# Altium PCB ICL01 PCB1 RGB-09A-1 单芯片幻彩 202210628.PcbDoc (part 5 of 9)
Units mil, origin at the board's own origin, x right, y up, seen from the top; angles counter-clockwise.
Board outline 17436.43 x 6581.89 mil, 2 copper layers (Top Layer, Bottom Layer), stack 65.792 mil thick; 425 components, 516 nets, 1625 pads, 2772 vias.
Unrouted connection lines stored in the file: 1.
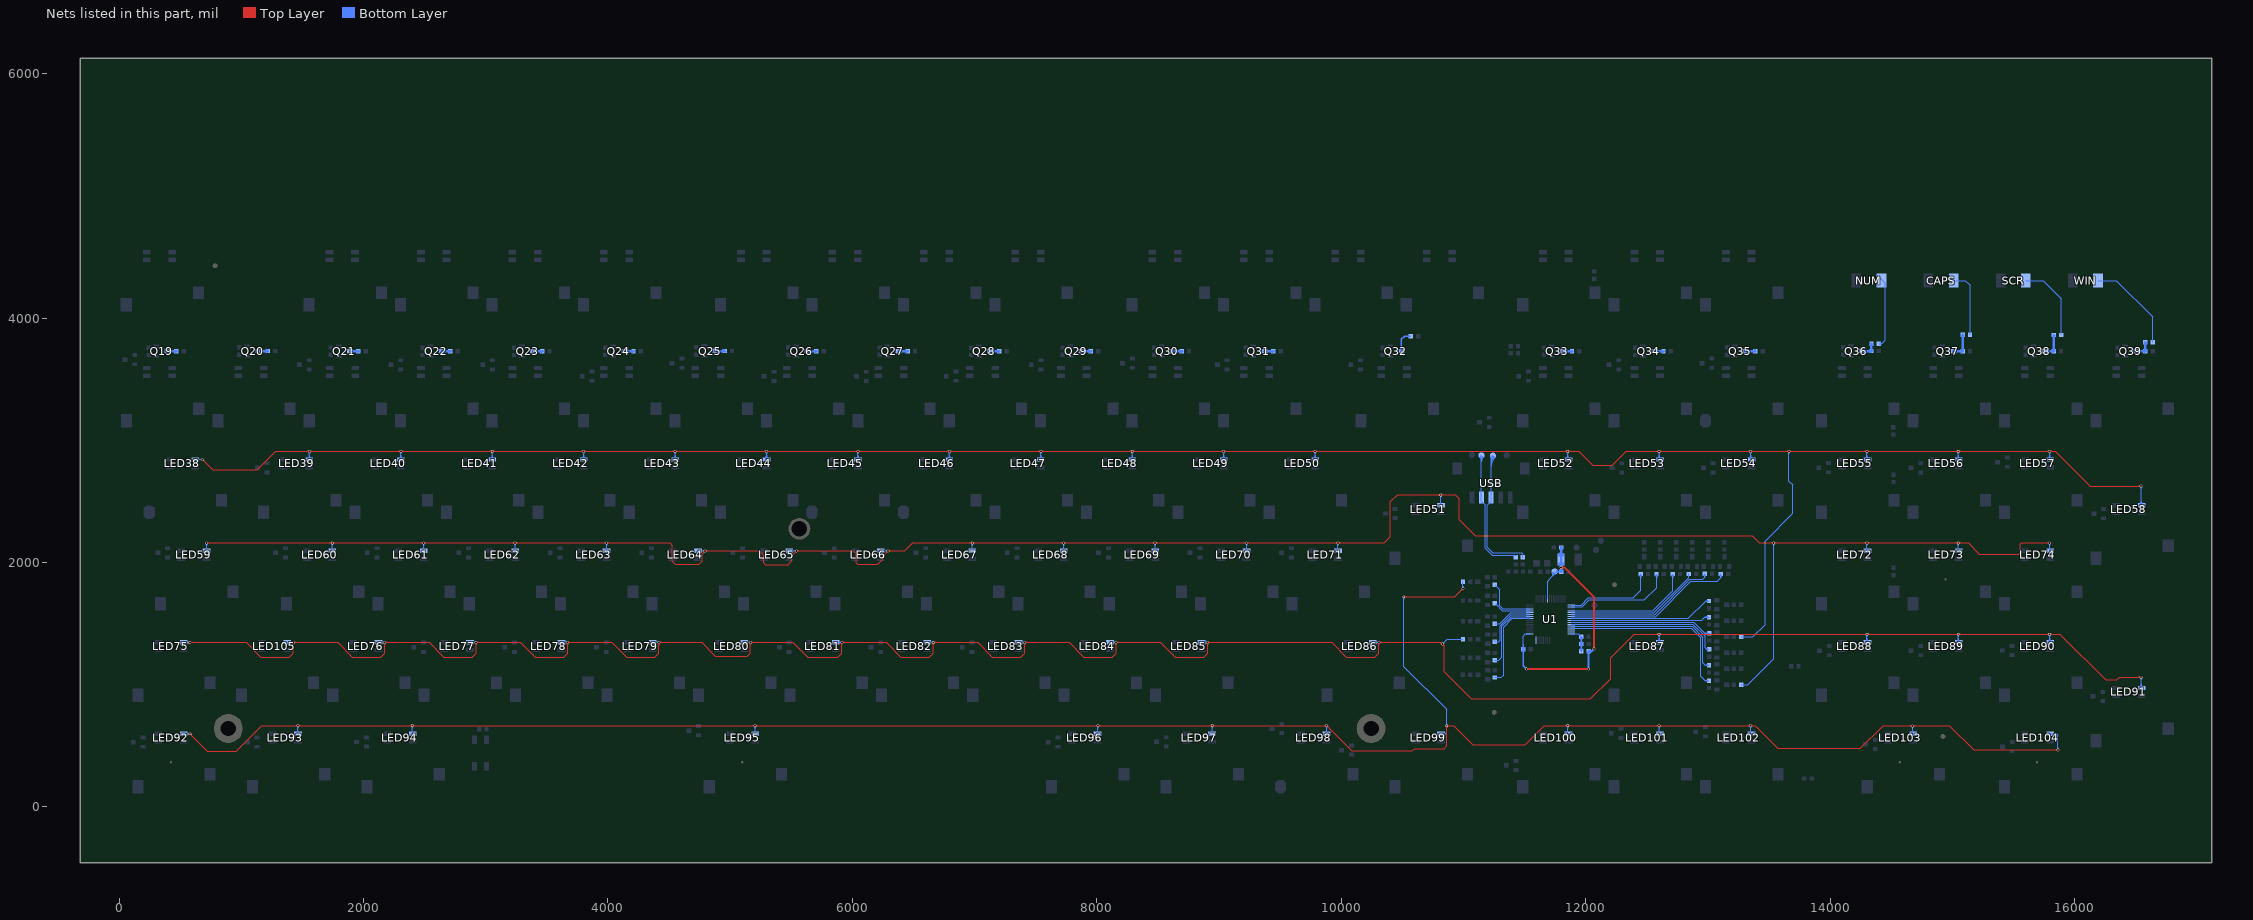
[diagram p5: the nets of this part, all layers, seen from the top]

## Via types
v1: diameter 23.62, hole 15.75, Top Layer to Bottom Layer, tented both sides, 2766 vias
v2: diameter 19.68, hole 11.81, Top Layer to Bottom Layer, tented both sides, 6 vias

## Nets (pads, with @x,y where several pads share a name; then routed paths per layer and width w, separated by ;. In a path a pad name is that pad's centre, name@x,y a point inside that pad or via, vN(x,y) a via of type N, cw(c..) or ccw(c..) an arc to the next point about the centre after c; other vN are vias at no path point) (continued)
GR2: LED38.G LED39.G LED40.G LED41.G LED42.G LED43.G LED44.G LED45.G LED46.G LED47.G LED48.G LED49.G LED50.G LED52.G LED53.G LED54.G LED55.G LED56.G LED57.G LED58.G RR9.2 | length 22150.5
  Top Layer w7.87: v1@682.41,2834.84 cw(c682.41,2815.83) 695.85,2829.28 cw(c709.3,2842.72) v1@690.29,2842.72 ; v1(682.41,2842.72) 768.34,2756.79 1132.05,2756.79 1284.13,2908.87 v1@11852.98,2908.87 ; 1538.45,2908.86 cw(c1538.45,2889.51) v1@1552.13,2903.19 ; 1538.93,2908.86 ccw(c1538.93,2927.53) v1@1552.13,2914.33 ; v1@1563.27,2903.19 cw(c1576.95,2889.51) 1576.95,2908.86 ; v1@1563.27,2914.33 ccw(c1576.47,2927.53) 1576.47,2908.86 ; 2286.48,2908.86 cw(c2286.48,2889.51) v1@2300.16,2903.19 ; 2286.96,2908.86 ccw(c2286.96,2927.53) v1@2300.16,2914.33 ; v1@2311.3,2903.19 cw(c2324.98,2889.51) 2324.98,2908.86 ; v1@2311.3,2914.33 ccw(c2324.5,2927.53) 2324.5,2908.86 ; 3034.51,2908.86 cw(c3034.51,2889.51) v1@3048.2,2903.19 ; 3035,2908.86 ccw(c3035,2927.53) v1@3048.2,2914.33 ; v1@3059.33,2903.19 cw(c3073.01,2889.51) 3073.01,2908.86 ; v1@3059.33,2914.33 ccw(c3072.53,2927.53) 3072.53,2908.86 ; 3782.54,2908.86 cw(c3782.54,2889.51) v1@3796.23,2903.19 ; 3783.03,2908.86 ccw(c3783.03,2927.53) v1@3796.23,2914.33 ; v1@3807.36,2903.19 cw(c3821.05,2889.51) 3821.05,2908.86 ; v1@3807.36,2914.33 ccw(c3820.56,2927.53) 3820.56,2908.86 ; 4530.58,2908.86 cw(c4530.58,2889.51) v1@4544.26,2903.19 ; 4531.06,2908.86 ccw(c4531.06,2927.53) v1@4544.26,2914.33 ; v1@4555.39,2903.19 cw(c4569.08,2889.51) 4569.08,2908.86 ; v1@4555.39,2914.33 ccw(c4568.59,2927.53) 4568.59,2908.86 ; 5278.61,2908.86 cw(c5278.61,2889.51) v1@5292.29,2903.19 ; 5279.09,2908.86 ccw(c5279.09,2927.53) v1@5292.29,2914.33 ; v1@5303.43,2903.19 cw(c5317.11,2889.51) 5317.11,2908.86 ; v1@5303.43,2914.33 ccw(c5316.63,2927.53) 5316.63,2908.86 ; 6026.64,2908.86 cw(c6026.64,2889.51) v1@6040.32,2903.19 ; 6027.12,2908.86 ccw(c6027.12,2927.53) v1@6040.32,2914.33 ; v1@6051.46,2903.19 cw(c6065.14,2889.51) 6065.14,2908.86 ; v1@6051.46,2914.33 ccw(c6064.66,2927.53) 6064.66,2908.86 ; 6774.67,2908.86 cw(c6774.67,2889.51) v1@6788.35,2903.19 ; 6775.15,2908.86 ccw(c6775.15,2927.53) v1@6788.35,2914.33 ; v1@6799.49,2903.19 cw(c6813.17,2889.51) 6813.17,2908.86 ; v1@6799.49,2914.33 ccw(c6812.69,2927.53) 6812.69,2908.86 ; 7522.7,2908.86 cw(c7522.7,2889.51) v1@7536.38,2903.19 ; 7523.18,2908.86 ccw(c7523.18,2927.53) v1@7536.38,2914.33 ; v1@7547.52,2903.19 cw(c7561.2,2889.51) 7561.2,2908.86 ; v1@7547.52,2914.33 ccw(c7560.72,2927.53) 7560.72,2908.86 ; 8270.73,2908.86 cw(c8270.73,2889.51) v1@8284.42,2903.19 ; 8271.22,2908.86 ccw(c8271.22,2927.53) v1@8284.42,2914.33 ; v1@8295.55,2903.19 cw(c8309.24,2889.51) 8309.24,2908.86 ; v1@8295.55,2914.33 ccw(c8308.75,2927.53) 8308.75,2908.86 ; 9018.76,2908.86 cw(c9018.76,2889.51) v1@9032.45,2903.19 ; 9019.25,2908.86 ccw(c9019.25,2927.53) v1@9032.45,2914.33 ; v1@9043.58,2903.19 cw(c9057.27,2889.51) 9057.27,2908.86 ; v1@9043.58,2914.33 ccw(c9056.78,2927.53) 9056.78,2908.86 ; 9766.8,2908.86 cw(c9766.8,2889.51) v1@9780.48,2903.19 ; 9767.28,2908.86 ccw(c9767.28,2927.53) v1@9780.48,2914.33 ; v1@9791.62,2903.19 cw(c9805.3,2889.51) 9805.3,2908.86 ; v1@9791.62,2914.33 ccw(c9804.82,2927.53) 9804.82,2908.86 ; 11833.71,2908.87 cw(c11833.71,2889.5) v1@11847.41,2903.19 ; 11834.22,2908.87 ccw(c11834.22,2927.52) v1@11847.41,2914.33 ; v1(11852.98,2908.76) 11941.7,2908.76 12055.64,2794.82 12217.49,2794.82 12331.53,2908.87 v1(13663.07,2908.87) 15842.45,2908.87 16126.95,2624.37 v1(16543.92,2624.37) ; v1@11858.54,2903.19 cw(c11871.99,2889.75) 11871.99,2908.76 cw(c11871.99,2927.77) v1@11858.54,2914.33 ; 12581.76,2908.86 cw(c12581.76,2889.51) v1@12595.44,2903.19 ; 12582.24,2908.86 ccw(c12582.24,2927.53) v1@12595.44,2914.33 ; v1@12606.58,2903.19 cw(c12620.26,2889.51) 12620.26,2908.86 ; v1@12606.58,2914.33 ccw(c12619.78,2927.53) 12619.78,2908.86 ; 13329.79,2908.86 cw(c13329.79,2889.51) v1@13343.47,2903.19 ; 13330.27,2908.86 ccw(c13330.27,2927.53) v1@13343.47,2914.33 ; v1@13354.61,2903.19 cw(c13368.29,2889.51) 13368.29,2908.86 ; v1@13354.61,2914.33 ccw(c13367.81,2927.53) 13367.81,2908.86 ; v1@13657.5,2903.3 ccw(c13644.06,2889.86) 13644.06,2908.87 ccw(c13644.06,2927.88) v1@13657.5,2914.43 ; v1@13668.64,2903.3 cw(c13682.08,2889.86) 13682.08,2908.87 cw(c13682.08,2927.88) v1@13668.64,2914.43 ; 14280.58,2908.86 cw(c14280.58,2889.51) v1@14294.26,2903.19 ; 14281.06,2908.86 ccw(c14281.06,2927.53) v1@14294.26,2914.33 ; v1@14305.39,2903.19 cw(c14319.08,2889.51) 14319.08,2908.86 ; v1@14305.39,2914.33 ccw(c14318.59,2927.53) 14318.59,2908.86 ; 15028.61,2908.86 cw(c15028.61,2889.51) v1@15042.29,2903.19 ; 15029.09,2908.86 ccw(c15029.09,2927.53) v1@15042.29,2914.33 ; v1@15053.43,2903.19 cw(c15067.11,2889.51) 15067.11,2908.86 ; v1@15053.43,2914.33 ccw(c15066.63,2927.53) 15066.63,2908.86 ; v1@15790.32,2903.29 ccw(c15776.88,2889.85) 15776.88,2908.86 ccw(c15776.88,2927.87) v1@15790.32,2914.43 ; v1@15801.46,2903.29 cw(c15814.9,2889.85) 15814.9,2908.86 cw(c15814.9,2927.87) v1@15801.46,2914.43 ; v1@16538.36,2618.8 ccw(c16524.91,2605.36) 16524.91,2624.37 ccw(c16524.91,2643.38) v1@16538.36,2629.94
  Bottom Layer w7.87: LED38.G@622.66,2842.72 v1(682.41,2842.72) ; v1@676.84,2837.15 ccw(c663.4,2823.71) 663.4,2842.72 ccw(c663.4,2861.73) v1@676.84,2848.29 ; LED39.G@1547.96,2852.46 ccw(c1524.43,2875.98) 1557.7,2875.98 ccw(c1590.97,2875.98) LED39.G@1567.44,2852.46 ; v1@1552.13,2903.19 cw(c1538.69,2889.75) 1557.7,2889.75 cw(c1576.71,2889.75) v1@1563.27,2903.19 ; LED39.G@1557.7,2842.72 v1(1557.7,2908.76) ; LED40.G@2295.99,2852.46 ccw(c2272.47,2875.98) 2305.73,2875.98 ccw(c2339,2875.98) LED40.G@2315.48,2852.46 ; v1@2300.16,2903.19 cw(c2286.72,2889.75) 2305.73,2889.75 cw(c2324.74,2889.75) v1@2311.3,2903.19 ; LED40.G@2305.73,2842.72 v1(2305.73,2908.76) ; LED41.G@3044.02,2852.46 ccw(c3020.5,2875.98) 3053.76,2875.98 ccw(c3087.03,2875.98) LED41.G@3063.51,2852.46 ; v1@3048.2,2903.19 cw(c3034.75,2889.75) 3053.76,2889.75 cw(c3072.77,2889.75) v1@3059.33,2903.19 ; LED41.G@3053.76,2842.72 v1(3053.76,2908.76) ; LED42.G@3792.05,2852.46 ccw(c3768.53,2875.98) 3801.8,2875.98 ccw(c3835.06,2875.98) LED42.G@3811.54,2852.46 ; v1@3796.23,2903.19 cw(c3782.79,2889.75) 3801.8,2889.75 cw(c3820.81,2889.75) v1@3807.36,2903.19 ; LED42.G@3801.8,2842.72 v1(3801.8,2908.76) ; LED43.G@4540.08,2852.46 ccw(c4516.56,2875.98) 4549.83,2875.98 ccw(c4583.09,2875.98) LED43.G@4559.57,2852.46 ; v1@4544.26,2903.19 cw(c4530.82,2889.75) 4549.83,2889.75 cw(c4568.84,2889.75) v1@4555.39,2903.19 ; LED43.G@4549.83,2842.72 v1(4549.83,2908.76) ; LED44.G@5288.12,2852.46 ccw(c5264.59,2875.98) 5297.86,2875.98 ccw(c5331.13,2875.98) LED44.G@5307.6,2852.46 ; v1@5292.29,2903.19 cw(c5278.85,2889.75) 5297.86,2889.75 cw(c5316.87,2889.75) v1@5303.43,2903.19 ; LED44.G@5297.86,2842.72 v1(5297.86,2908.76) ; LED45.G@6036.15,2852.46 ccw(c6012.62,2875.98) 6045.89,2875.98 ccw(c6079.16,2875.98) LED45.G@6055.63,2852.46 ; v1@6040.32,2903.19 cw(c6026.88,2889.75) 6045.89,2889.75 cw(c6064.9,2889.75) v1@6051.46,2903.19 ; LED45.G@6045.89,2842.72 v1(6045.89,2908.76) ; LED46.G@6784.18,2852.46 ccw(c6760.66,2875.98) 6793.92,2875.98 ccw(c6827.19,2875.98) LED46.G@6803.67,2852.46 ; v1@6788.35,2903.19 cw(c6774.91,2889.75) 6793.92,2889.75 cw(c6812.93,2889.75) v1@6799.49,2903.19 ; LED46.G@6793.92,2842.72 v1(6793.92,2908.76) ; LED47.G@7532.21,2852.46 ccw(c7508.69,2875.98) 7541.95,2875.98 ccw(c7575.22,2875.98) LED47.G@7551.7,2852.46 ; v1@7536.38,2903.19 cw(c7522.94,2889.75) 7541.95,2889.75 cw(c7560.96,2889.75) v1@7547.52,2903.19 ; LED47.G@7541.95,2842.72 v1(7541.95,2908.76) ; LED48.G@8280.24,2852.46 ccw(c8256.72,2875.98) 8289.98,2875.98 ccw(c8323.25,2875.98) LED48.G@8299.73,2852.46 ; v1@8284.42,2903.19 cw(c8270.98,2889.75) 8289.98,2889.75 cw(c8308.99,2889.75) v1@8295.55,2903.19 ; LED48.G@8289.98,2842.72 v1(8289.98,2908.76) ; LED49.G@9028.27,2852.46 ccw(c9004.75,2875.98) 9038.02,2875.98 ccw(c9071.28,2875.98) LED49.G@9047.76,2852.46 ; v1@9032.45,2903.19 cw(c9019.01,2889.75) 9038.02,2889.75 cw(c9057.03,2889.75) v1@9043.58,2903.19 ; LED49.G@9038.02,2842.72 v1(9038.02,2908.76) ; LED50.G@9776.3,2852.46 ccw(c9752.78,2875.98) 9786.05,2875.98 ccw(c9819.31,2875.98) LED50.G@9795.79,2852.46 ; v1@9780.48,2903.19 cw(c9767.04,2889.75) 9786.05,2889.75 cw(c9805.06,2889.75) v1@9791.62,2903.19 ; LED50.G@9786.05,2842.72 v1(9786.05,2908.76) ; LED52.G@11843.23,2852.46 ccw(c11819.71,2875.98) 11852.98,2875.98 ccw(c11886.24,2875.98) LED52.G@11862.72,2852.46 ; v1@11847.41,2903.19 cw(c11833.97,2889.75) 11852.98,2889.75 cw(c11871.99,2889.75) v1@11858.54,2903.19 ; LED52.G@11852.98,2842.72 v1(11852.98,2908.76) ; LED53.G@12591.26,2852.46 ccw(c12567.74,2875.98) 12601.01,2875.98 ccw(c12634.27,2875.98) LED53.G@12610.75,2852.46 ; v1@12595.44,2903.19 cw(c12582,2889.75) 12601.01,2889.75 cw(c12620.02,2889.75) v1@12606.58,2903.19 ; LED53.G@12601.01,2842.72 v1(12601.01,2908.76) ; RR9.2@13272.34,1391.22 13365.96,1391.22 13467.2,1492.46 13467.2,2175.6 13693.49,2401.88 13693.49,2634.35 13663.07,2664.77 v1(13663.07,2908.87) ; LED54.G@13339.3,2852.46 ccw(c13315.77,2875.98) 13349.04,2875.98 ccw(c13382.31,2875.98) LED54.G@13358.78,2852.46 ; v1@13343.47,2903.19 cw(c13330.03,2889.75) 13349.04,2889.75 cw(c13368.05,2889.75) v1@13354.61,2903.19 ; LED54.G@13349.04,2842.72 v1(13349.04,2908.76) ; v1@13657.5,2903.3 cw(c13644.06,2889.86) 13663.07,2889.86 cw(c13682.08,2889.86) v1@13668.64,2903.3 ; LED55.G@14290.08,2852.46 ccw(c14266.56,2875.98) 14299.83,2875.98 ccw(c14333.09,2875.98) LED55.G@14309.57,2852.46 ; v1@14294.26,2903.19 cw(c14280.82,2889.75) 14299.83,2889.75 cw(c14318.84,2889.75) v1@14305.39,2903.19 ; LED55.G@14299.83,2842.72 v1(14299.83,2908.76) ; LED56.G@15038.12,2852.46 ccw(c15014.59,2875.98) 15047.86,2875.98 ccw(c15081.13,2875.98) LED56.G@15057.6,2852.46 ; v1@15042.29,2903.19 cw(c15028.85,2889.75) 15047.86,2889.75 cw(c15066.87,2889.75) v1@15053.43,2903.19 ; LED56.G@15047.86,2842.72 v1(15047.86,2908.76) ; LED57.G@15786.15,2852.46 ccw(c15762.62,2875.98) 15795.89,2875.98 ccw(c15829.16,2875.98) LED57.G@15805.63,2852.46 ; v1@15790.32,2903.29 cw(c15776.88,2889.85) 15795.89,2889.85 cw(c15814.9,2889.85) v1@15801.46,2903.29 ; LED57.G@15795.89,2842.72 v1(15795.89,2908.86) ; LED58.G@16534.18,2478.45 ccw(c16510.66,2501.97) 16543.92,2501.97 ccw(c16577.19,2501.97) LED58.G@16553.67,2478.45 ; v1@16538.36,2618.8 cw(c16524.91,2605.36) 16543.92,2605.36 cw(c16562.93,2605.36) v1@16549.49,2618.8 ; LED58.G@16543.92,2468.7 v1(16543.92,2624.37)
GR3: LED51.G LED59.G LED60.G LED61.G LED62.G LED63.G LED64.G LED65.G LED66.G LED67.G LED68.G LED69.G LED70.G LED71.G LED72.G LED73.G LED74.G RR12.2 | length 20324.4
  Top Layer w7.87: v1@716.47,2160.83 4505.83,2160.83 4528.17,2138.49 4528.17,2009.39 4552.4,1985.16 4745.09,1985.16 4770.1,2010.17 4770.1,2069.15 v1(4795.64,2094.69) 5238.05,2094.69 5273.75,2058.98 5273.75,1996.1 5286.6,1983.25 5475.55,1983.25 5504.8,2012.5 5504.8,2055.82 v1(5543.67,2094.69) 6007.74,2094.69 6030.85,2071.58 6030.85,1999.66 6045.64,1984.88 6208.27,1984.88 6250.16,2026.77 6250.16,2053.15 v1(6291.7,2094.69) 6429.35,2094.69 6495.49,2160.83 10352.84,2160.83 10402.69,2210.68 10402.69,2494.94 10461.3,2553.55 10933.17,2553.55 10964.7,2522.02 10964.7,2350.29 11094.3,2220.69 13360.89,2220.69 13420.71,2160.88 13538.03,2160.88 v1(13538.07,2160.83) 15128.19,2160.83 15220.92,2068.1 15542.48,2068.1 15554.24,2079.85 15554.24,2149.74 15564.77,2160.27 v1(15795.85,2160.27) ; v1@722.03,2153.3 cw(c740.22,2135.11) 740.22,2160.83 ; v1@722.03,2164.44 ccw(c730.73,2173.13) 730.73,2160.83 ; v1@1739.14,2155.27 ccw(c1725.7,2141.83) 1725.7,2160.84 ccw(c1725.7,2179.85) v1@1739.14,2166.41 ; v1@1750.28,2155.27 cw(c1763.72,2141.83) 1763.72,2160.84 cw(c1763.72,2179.85) v1@1750.28,2166.41 ; v1@2487.17,2155.27 ccw(c2473.73,2141.83) 2473.73,2160.84 ccw(c2473.73,2179.85) v1@2487.17,2166.41 ; v1@2498.31,2155.27 cw(c2511.75,2141.83) 2511.75,2160.84 cw(c2511.75,2179.85) v1@2498.31,2166.41 ; v1@3235.2,2155.27 ccw(c3221.76,2141.83) 3221.76,2160.84 ccw(c3221.76,2179.85) v1@3235.2,2166.41 ; v1@3246.34,2155.27 cw(c3259.78,2141.83) 3259.78,2160.84 cw(c3259.78,2179.85) v1@3246.34,2166.41 ; v1@3983.24,2155.27 ccw(c3969.79,2141.83) 3969.79,2160.84 ccw(c3969.79,2179.85) v1@3983.24,2166.41 ; v1@3994.37,2155.27 cw(c4007.81,2141.83) 4007.81,2160.84 cw(c4007.81,2179.85) v1@3994.37,2166.41 ; v1@4787.76,2094.69 cw(c4768.75,2094.69) 4782.19,2081.25 cw(c4795.64,2067.8) v1@4795.64,2086.81 ; v1@4801.2,2089.12 cw(c4814.65,2075.68) 4814.65,2094.69 cw(c4814.65,2113.7) v1@4801.2,2100.25 ; v1@5535.79,2094.69 cw(c5516.78,2094.69) 5530.23,2081.25 cw(c5543.67,2067.8) v1@5543.67,2086.81 ; v1@5549.24,2089.12 cw(c5562.68,2075.68) 5562.68,2094.69 cw(c5562.68,2113.7) v1@5549.24,2100.25 ; v1@6283.83,2094.69 cw(c6264.82,2094.69) 6278.26,2081.25 cw(c6291.7,2067.8) v1@6291.7,2086.81 ; v1@6297.27,2089.12 cw(c6310.71,2075.68) 6310.71,2094.69 cw(c6310.71,2113.7) v1@6297.27,2100.25 ; v1@6975.36,2155.27 ccw(c6961.92,2141.83) 6961.92,2160.84 ccw(c6961.92,2179.85) v1@6975.36,2166.41 ; v1@6986.5,2155.27 cw(c6999.94,2141.83) 6999.94,2160.84 cw(c6999.94,2179.85) v1@6986.5,2166.41 ; v1@7723.39,2155.27 ccw(c7709.95,2141.83) 7709.95,2160.84 ccw(c7709.95,2179.85) v1@7723.39,2166.41 ; v1@7734.53,2155.27 cw(c7747.97,2141.83) 7747.97,2160.84 cw(c7747.97,2179.85) v1@7734.53,2166.41 ; v1@8471.42,2155.27 ccw(c8457.98,2141.83) 8457.98,2160.84 ccw(c8457.98,2179.85) v1@8471.42,2166.41 ; v1@8482.56,2155.27 cw(c8496,2141.83) 8496,2160.84 cw(c8496,2179.85) v1@8482.56,2166.41 ; v1@9219.46,2155.27 ccw(c9206.01,2141.83) 9206.01,2160.84 ccw(c9206.01,2179.85) v1@9219.46,2166.41 ; v1@9230.59,2155.27 cw(c9244.03,2141.83) 9244.03,2160.84 cw(c9244.03,2179.85) v1@9230.59,2166.41 ; v1@9967.49,2155.27 ccw(c9954.05,2141.83) 9954.05,2160.84 ccw(c9954.05,2179.85) v1@9967.49,2166.41 ; v1@9978.62,2155.27 cw(c9992.07,2141.83) 9992.07,2160.84 cw(c9992.07,2179.85) v1@9978.62,2166.41 ; 10795.03,2553.55 ccw(c10795.03,2572.71) v1@10808.58,2559.16 ; 10795.25,2553.55 cw(c10795.25,2534.7) v1@10808.58,2548.03 ; v1@10819.72,2548.03 cw(c10833.05,2534.7) 10833.05,2553.55 ; v1@10819.72,2559.16 ccw(c10833.27,2572.71) 10833.27,2553.55 ; 13518.96,2160.88 cw(c13518.96,2141.73) v1@13532.5,2155.27 ; 13519.16,2160.88 ccw(c13519.16,2179.75) v1@13532.5,2166.4 ; v1@13543.64,2155.27 cw(c13557.08,2141.83) 13557.08,2160.83 cw(c13557.08,2179.84) v1@13543.64,2166.4 ; v1@14294.26,2155.27 ccw(c14280.82,2141.83) 14280.82,2160.84 ccw(c14280.82,2179.85) v1@14294.26,2166.41 ; v1@14305.39,2155.27 cw(c14318.84,2141.83) 14318.84,2160.84 cw(c14318.84,2179.85) v1@14305.39,2166.41 ; v1@15042.29,2155.27 ccw(c15028.85,2141.83) 15028.85,2160.84 ccw(c15028.85,2179.85) v1@15042.29,2166.41 ; v1@15053.43,2155.27 cw(c15066.87,2141.83) 15066.87,2160.84 cw(c15066.87,2179.85) v1@15053.43,2166.41 ; v1@15790.28,2154.71 ccw(c15776.84,2141.26) 15776.84,2160.27 ccw(c15776.84,2179.28) v1@15790.28,2165.84
  Bottom Layer w7.87: v1@710.9,2153.3 cw(c698.18,2140.58) 716.17,2140.58 ; LED59.G@716.17,2094.69 v1@716.17,2160.24 ; 716.17,2139.14 cw(c736.2,2139.14) v1@722.03,2153.3 ; v1@1739.14,2155.27 cw(c1725.7,2141.83) 1744.71,2141.83 cw(c1763.72,2141.83) v1@1750.28,2155.27 ; LED60.G@1744.71,2094.69 v1(1744.71,2160.84) ; v1@2487.17,2155.27 cw(c2473.73,2141.83) 2492.74,2141.83 cw(c2511.75,2141.83) v1@2498.31,2155.27 ; LED61.G@2492.74,2094.69 v1(2492.74,2160.84) ; v1@3235.2,2155.27 cw(c3221.76,2141.83) 3240.77,2141.83 cw(c3259.78,2141.83) v1@3246.34,2155.27 ; LED62.G@3240.77,2094.69 v1(3240.77,2160.84) ; v1@3983.24,2155.27 cw(c3969.79,2141.83) 3988.8,2141.83 cw(c4007.81,2141.83) v1@3994.37,2155.27 ; LED63.G@3988.8,2094.69 v1(3988.8,2160.84) ; LED64.G@4736.83,2094.69 v1(4795.64,2094.69) ; v1@4790.07,2089.12 ccw(c4776.63,2075.68) 4776.63,2094.69 ccw(c4776.63,2113.7) v1@4790.07,2100.25 ; LED65.G@5484.87,2094.69 v1(5543.67,2094.69) ; v1@5538.1,2089.12 ccw(c5524.66,2075.68) 5524.66,2094.69 ccw(c5524.66,2113.7) v1@5538.1,2100.25 ; LED66.G@6232.9,2094.69 v1(6291.7,2094.69) ; v1@6286.13,2089.12 ccw(c6272.69,2075.68) 6272.69,2094.69 ccw(c6272.69,2113.7) v1@6286.13,2100.25 ; v1@6975.36,2155.27 cw(c6961.92,2141.83) 6980.93,2141.83 cw(c6999.94,2141.83) v1@6986.5,2155.27 ; LED67.G@6980.93,2094.69 v1(6980.93,2160.84) ; v1@7723.39,2155.27 cw(c7709.95,2141.83) 7728.96,2141.83 cw(c7747.97,2141.83) v1@7734.53,2155.27 ; LED68.G@7728.96,2094.69 v1(7728.96,2160.84) ; v1@8471.42,2155.27 cw(c8457.98,2141.83) 8476.99,2141.83 cw(c8496,2141.83) v1@8482.56,2155.27 ; LED69.G@8476.99,2094.69 v1(8476.99,2160.84) ; v1@9219.46,2155.27 cw(c9206.01,2141.83) 9225.02,2141.83 cw(c9244.03,2141.83) v1@9230.59,2155.27 ; LED70.G@9225.02,2094.69 v1(9225.02,2160.84) ; v1@9967.49,2155.27 cw(c9954.05,2141.83) 9973.06,2141.83 cw(c9992.07,2141.83) v1@9978.62,2155.27 ; LED71.G@9973.06,2094.69 v1(9973.06,2160.84) ; v1@10808.58,2548.03 cw(c10795.14,2534.59) 10814.15,2534.59 cw(c10833.16,2534.59) v1@10819.72,2548.03 ; LED51.G@10814.15,2468.64 v1(10814.15,2553.6) ; RR12.2@13272.34,998.6 13325.16,998.6 13538.07,1211.51 v1(13538.07,2160.83) ; v1@13532.5,2155.27 cw(c13519.06,2141.83) 13538.07,2141.83 cw(c13557.08,2141.83) v1@13543.64,2155.27 ; v1@14294.26,2155.27 cw(c14280.82,2141.83) 14299.83,2141.83 cw(c14318.84,2141.83) v1@14305.39,2155.27 ; LED72.G@14299.83,2094.69 v1(14299.83,2160.84) ; v1@15042.29,2155.27 cw(c15028.85,2141.83) 15047.86,2141.83 cw(c15066.87,2141.83) v1@15053.43,2155.27 ; LED73.G@15047.86,2094.69 v1(15047.86,2160.84) ; v1@15790.28,2154.71 cw(c15776.75,2141.17) 15795.89,2141.17 ; LED74.G@15795.89,2094.69 v1@15795.89,2160.34 ; 15795.89,2141.36 cw(c15814.76,2141.36) v1@15801.42,2154.71
  other v1: 716.47,2158.87
GR4: LED75.G LED76.G LED77.G LED78.G LED79.G LED80.G LED81.G LED82.G LED83.G LED84.G LED85.G LED86.G LED87.G LED88.G LED89.G LED90.G LED91.G LED105.G RR15.2 | length 21513
  Top Layer w7.87: v1(579.16,1345.72) 1040.61,1345.72 1160.37,1225.97 1393.14,1225.97 1425.62,1258.44 v1(1425.62,1345.72) 1788.64,1345.72 1908.4,1225.97 2141.17,1225.97 2173.65,1258.44 v1(2173.65,1345.72) 2536.68,1345.72 2656.43,1225.97 2889.2,1225.97 2921.68,1258.44 v1(2921.68,1345.72) 3284.71,1345.72 3404.47,1225.97 3637.23,1225.97 3669.71,1258.44 v1(3669.71,1345.72) 4032.74,1345.72 4152.5,1225.97 4385.26,1225.97 4417.74,1258.44 v1(4417.74,1345.72) 4766.62,1345.72 4878.03,1234.31 5141.64,1234.31 5165.77,1258.44 v1(5165.77,1345.72) 5514.14,1345.72 5633.9,1225.97 5881.33,1225.97 5913.81,1258.44 v1(5913.81,1345.72) 6276.83,1345.72 6396.59,1225.97 6629.36,1225.97 6661.84,1258.44 v1(6661.84,1345.72) 7024.86,1345.72 7144.62,1225.97 7377.39,1225.97 7409.87,1258.44 v1(7409.87,1345.72) 7772.9,1345.72 7892.65,1225.97 8125.42,1225.97 8157.9,1258.44 v1(8157.9,1345.72) 8520.93,1345.72 8640.69,1225.97 8873.45,1225.97 8905.93,1258.44 v1(8905.93,1345.72) 9922.5,1345.72 10042.82,1225.4 10274.47,1225.4 10307.51,1258.44 v1(10307.51,1345.72) 10813.61,1345.72 v1(10827.37,1331.96) 10841.13,1318.2 10841.13,1106.94 11061.95,886.12 12038.94,886.12 12203.57,1050.75 12203.57,1219.83 12396.59,1412.85 v1(12601.01,1412.88) 14059.78,1412.83 14807.81,1412.82 15557.75,1412.8 15878.81,1412.8 16252.93,1038.68 16345.17,1038.68 16367.94,1061.46 v1(16543.92,1061.46) ; v1@584.73,1340.16 cw(c598.17,1326.71) 598.17,1345.72 cw(c598.17,1364.73) v1@584.73,1351.29 ; v1@1420.05,1340.16 cw(c1406.61,1326.71) 1425.62,1326.71 cw(c1444.63,1326.71) 1431.18,1340.16 cw(c1444.63,1326.71) 1444.63,1345.72 cw(c1444.63,1364.73) v1@1431.18,1351.29 ; v1@2168.08,1340.16 cw(c2154.64,1326.71) 2173.65,1326.71 cw(c2192.66,1326.71) 2179.22,1340.16 cw(c2192.66,1326.71) 2192.66,1345.72 cw(c2192.66,1364.73) v1@2179.22,1351.29 ; v1@2916.11,1340.16 cw(c2902.67,1326.71) 2921.68,1326.71 cw(c2940.69,1326.71) 2927.25,1340.16 cw(c2940.69,1326.71) 2940.69,1345.72 cw(c2940.69,1364.73) v1@2927.25,1351.29 ; v1@3664.14,1340.16 cw(c3650.7,1326.71) 3669.71,1326.71 cw(c3688.72,1326.71) 3675.28,1340.16 cw(c3688.72,1326.71) 3688.72,1345.72 cw(c3688.72,1364.73) v1@3675.28,1351.29 ; v1@4412.17,1340.16 cw(c4398.73,1326.71) 4417.74,1326.71 cw(c4436.75,1326.71) 4423.31,1340.16 cw(c4436.75,1326.71) 4436.75,1345.72 cw(c4436.75,1364.73) v1@4423.31,1351.29 ; v1@5160.21,1340.16 cw(c5146.76,1326.71) 5165.77,1326.71 cw(c5184.78,1326.71) 5171.34,1340.16 cw(c5184.78,1326.71) 5184.78,1345.72 cw(c5184.78,1364.73) v1@5171.34,1351.29 ; v1@5908.24,1340.16 cw(c5894.8,1326.71) 5913.81,1326.71 cw(c5932.81,1326.71) 5919.37,1340.16 cw(c5932.81,1326.71) 5932.81,1345.72 cw(c5932.81,1364.73) v1@5919.37,1351.29 ; v1@6656.27,1340.16 cw(c6642.83,1326.71) 6661.84,1326.71 cw(c6680.85,1326.71) 6667.4,1340.16 cw(c6680.85,1326.71) 6680.85,1345.72 cw(c6680.85,1364.73) v1@6667.4,1351.29 ; v1@7404.3,1340.16 cw(c7390.86,1326.71) 7409.87,1326.71 cw(c7428.88,1326.71) 7415.44,1340.16 cw(c7428.88,1326.71) 7428.88,1345.72 cw(c7428.88,1364.73) v1@7415.44,1351.29 ; v1@8152.33,1340.16 cw(c8138.89,1326.71) 8157.9,1326.71 cw(c8176.91,1326.71) 8163.47,1340.16 cw(c8176.91,1326.71) 8176.91,1345.72 cw(c8176.91,1364.73) v1@8163.47,1351.29 ; v1@8900.36,1340.16 cw(c8886.92,1326.71) 8905.93,1326.71 cw(c8924.94,1326.71) 8911.5,1340.16 cw(c8924.94,1326.71) 8924.94,1345.72 cw(c8924.94,1364.73) v1@8911.5,1351.29 ; v1@10301.94,1340.16 cw(c10288.5,1326.71) 10307.51,1326.71 cw(c10326.52,1326.71) 10313.07,1340.16 cw(c10326.52,1326.71) 10326.52,1345.72 cw(c10326.52,1364.73) v1@10313.07,1351.29 ; v1@10819.5,1331.96 ccw(c10800.49,1331.96) 10813.93,1345.41 ccw(c10827.37,1358.85) v1@10827.37,1339.84 ; v1@10827.37,1324.09 cw(c10827.37,1305.08) 10840.81,1318.52 cw(c10854.25,1331.96) v1@10835.24,1331.96 ; 12581.92,1412.85 ccw(c12581.92,1431.97) v1@12595.44,1418.45 ; 12582.07,1412.85 cw(c12582.07,1393.95) v1@12595.44,1407.31 ; v1@12606.58,1407.31 cw(c12619.94,1393.95) 12619.94,1412.85 ; v1@12606.58,1418.45 ccw(c12620.09,1431.97) 12620.09,1412.85 ; 15776.69,1412.8 ccw(c15776.69,1432.08) v1@15790.32,1418.45 ; 15777.07,1412.8 cw(c15777.07,1394.06) v1@15790.32,1407.31 ; v1@15801.46,1407.31 cw(c15814.71,1394.06) 15814.71,1412.8 ; v1@15801.46,1418.45 ccw(c15815.09,1432.08) 15815.09,1412.8 ; v1@16538.35,1055.89 ccw(c16524.91,1042.45) 16524.91,1061.46 ccw(c16524.91,1080.47) v1@16538.35,1067.02 ; v1@14305.39,1407.31 cw(c14318.69,1394.01) 14318.69,1412.82 ccw(c14318.69,1394.01) v1@14305.39,1407.31 ; v1@14305.39,1418.45 ccw(c14318.98,1432.03) 14318.98,1412.82 cw(c14318.98,1432.03) v1@14305.39,1418.45 ; v1@15053.43,1407.31 cw(c15066.7,1394.04) 15066.7,1412.81 ccw(c15066.7,1394.04) v1@15053.43,1407.31 ; v1@15053.43,1418.45 ccw(c15067.04,1432.06) 15067.04,1412.81 cw(c15067.04,1432.06) v1@15053.43,1418.45
  Bottom Layer w7.87: LED75.G@539.74,1345.72 v1(579.16,1345.72) ; v1@573.59,1340.16 ccw(c560.15,1326.71) 560.15,1345.72 ccw(c560.15,1364.73) v1@573.59,1351.29 ; LED105.G@1386.19,1345.72 v1(1425.62,1345.72) ; v1@1420.05,1340.16 ccw(c1406.61,1326.71) 1406.61,1345.72 ccw(c1406.61,1364.73) v1@1420.05,1351.29 ; LED76.G@2134.22,1345.72 v1(2173.65,1345.72) ; v1@2168.08,1340.16 ccw(c2154.64,1326.71) 2154.64,1345.72 ccw(c2154.64,1364.73) v1@2168.08,1351.29 ; LED77.G@2882.26,1345.72 v1(2921.68,1345.72) ; v1@2916.11,1340.16 ccw(c2902.67,1326.71) 2902.67,1345.72 ccw(c2902.67,1364.73) v1@2916.11,1351.29 ; LED78.G@3630.29,1345.72 v1(3669.71,1345.72) ; v1@3664.14,1340.16 ccw(c3650.7,1326.71) 3650.7,1345.72 ccw(c3650.7,1364.73) v1@3664.14,1351.29 ; LED79.G@4378.32,1345.72 v1(4417.74,1345.72) ; v1@4412.17,1340.16 ccw(c4398.73,1326.71) 4398.73,1345.72 ccw(c4398.73,1364.73) v1@4412.17,1351.29 ; LED80.G@5126.35,1345.72 v1(5165.77,1345.72) ; v1@5160.21,1340.16 ccw(c5146.76,1326.71) 5146.76,1345.72 ccw(c5146.76,1364.73) v1@5160.21,1351.29 ; LED81.G@5874.38,1345.72 v1(5913.81,1345.72) ; v1@5908.24,1340.16 ccw(c5894.8,1326.71) 5894.8,1345.72 ccw(c5894.8,1364.73) v1@5908.24,1351.29 ; LED82.G@6622.41,1345.72 v1(6661.84,1345.72) ; v1@6656.27,1340.16 ccw(c6642.83,1326.71) 6642.83,1345.72 ccw(c6642.83,1364.73) v1@6656.27,1351.29 ; LED83.G@7370.44,1345.72 v1(7409.87,1345.72) ; v1@7404.3,1340.16 ccw(c7390.86,1326.71) 7390.86,1345.72 ccw(c7390.86,1364.73) v1@7404.3,1351.29 ; LED84.G@8118.48,1345.72 v1(8157.9,1345.72) ; v1@8152.33,1340.16 ccw(c8138.89,1326.71) 8138.89,1345.72 ccw(c8138.89,1364.73) v1@8152.33,1351.29 ; LED85.G@8866.51,1345.72 v1(8905.93,1345.72) ; v1@8900.36,1340.16 ccw(c8886.92,1326.71) 8886.92,1345.72 ccw(c8886.92,1364.73) v1@8900.36,1351.29 ; LED86.G@10268.08,1345.72 v1(10307.51,1345.72) ; v1@10301.94,1340.16 ccw(c10288.5,1326.71) 10288.5,1345.72 ccw(c10288.5,1364.73) v1@10301.94,1351.29 ; v1(10827.37,1331.96) 10868.13,1372.73 RR15.2@10995.55,1372.73 ; v1@10827.37,1339.84 ccw(c10827.37,1358.85) 10840.81,1345.41 ccw(c10854.25,1331.96) v1@10835.24,1331.96 ; LED87.G@12591.26,1356.4 ccw(c12567.74,1379.92) 12601.01,1379.92 ccw(c12634.27,1379.92) LED87.G@12610.75,1356.4 ; v1@12595.44,1407.31 cw(c12582,1393.87) 12601.01,1393.87 cw(c12620.02,1393.87) v1@12606.58,1407.31 ; LED87.G@12601.01,1346.66 v1(12601.01,1412.88) ; LED88.G@14290.08,1356.4 ccw(c14266.56,1379.92) 14299.83,1379.92 ccw(c14333.09,1379.92) LED88.G@14309.57,1356.4 ; v1@14294.26,1407.31 cw(c14280.82,1393.87) 14299.83,1393.87 cw(c14318.84,1393.87) v1@14305.39,1407.31 ; LED88.G@14299.83,1346.66 v1(14299.83,1412.88) ; LED89.G@15038.12,1356.4 ccw(c15014.59,1379.92) 15047.86,1379.92 ccw(c15081.13,1379.92) LED89.G@15057.6,1356.4 ; v1@15042.29,1407.31 cw(c15028.85,1393.87) 15047.86,1393.87 cw(c15066.87,1393.87) v1@15053.43,1407.31 ; LED89.G@15047.86,1346.66 v1(15047.86,1412.88) ; LED90.G@15786.15,1356.4 ccw(c15762.62,1379.92) 15795.89,1379.92 ccw(c15829.16,1379.92) LED90.G@15805.63,1356.4 ; v1@15790.32,1407.31 cw(c15776.88,1393.87) 15795.89,1393.87 cw(c15814.9,1393.87) v1@15801.46,1407.31 ; LED90.G@15795.89,1346.66 v1(15795.89,1412.88) ; LED91.G@16534.18,982.38 ccw(c16510.66,1005.91) 16543.92,1005.91 ccw(c16577.19,1005.91) LED91.G@16553.67,982.38 ; v1@16538.35,1055.89 cw(c16524.91,1042.45) 16543.92,1042.45 cw(c16562.93,1042.45) v1@16549.49,1055.89 ; LED91.G@16543.92,972.64 v1(16543.92,1061.46)
GR5: LED92.G LED93.G LED94.G LED95.G LED96.G LED97.G LED98.G LED99.G LED100.G LED101.G LED102.G LED103.G LED104.G RR18.2 | length 20098.4
  Top Layer w7.87: v1@580.64,590.75 cw(c580.64,571.74) 594.08,585.18 cw(c607.53,598.62) v1@588.52,598.62 ; v1(580.64,598.62) 721.75,457.52 958.93,457.52 1166.18,664.77 v1@8944.51,664.77 ; 1445.09,664.77 ccw(c1445.09,683.92) v1@1458.63,670.38 ; 1445.28,664.77 cw(c1445.28,645.9) v1@1458.63,659.24 ; v1@1469.76,659.24 cw(c1483.11,645.9) 1483.11,664.77 ; v1@1469.76,670.38 ccw(c1483.3,683.92) 1483.3,664.77 ; 2380.15,664.77 ccw(c2380.15,683.89) v1@2393.67,670.37 ; 2380.3,664.77 cw(c2380.3,645.87) v1@2393.67,659.24 ; v1@2404.8,659.24 cw(c2418.17,645.87) 2418.17,664.77 ; v1@2404.8,670.37 ccw(c2418.32,683.89) 2418.32,664.77 ; 5185.23,664.77 ccw(c5185.23,683.94) v1@5198.79,670.39 ; 5185.46,664.77 cw(c5185.46,645.92) v1@5198.79,659.25 ; v1@5209.92,659.25 cw(c5223.25,645.92) 5223.25,664.77 ; v1@5209.92,670.39 ccw(c5223.48,683.94) 5223.48,664.77 ; 7990.42,664.77 ccw(c7990.42,683.84) v1@8003.9,670.36 ; 7990.5,664.77 cw(c7990.5,645.82) v1@8003.9,659.22 ; v1@8015.04,659.22 cw(c8028.44,645.82) 8028.44,664.77 ; v1@8015.04,670.36 ccw(c8028.52,683.84) 8028.52,664.77 ; 8925.41,664.77 ccw(c8925.41,683.91) v1@8938.94,670.38 ; 8925.59,664.77 cw(c8925.59,645.89) v1@8938.94,659.24 ; v1(8944.51,664.81) v1@9879.51,664.81 ; v1@8950.08,659.24 cw(c8963.52,645.8) 8963.52,664.81 cw(c8963.52,683.82) v1@8950.08,670.38 ; 9860.53,664.81 cw(c9860.53,645.78) v1@9873.98,659.24 ; 9860.56,664.81 ccw(c9860.56,683.8) v1@9873.98,670.37 ; v1@9879.55,656.93 cw(c9879.55,638) 9892.94,651.38 ; v1(9879.55,664.8) 10085.07,459.26 10581.3,459.26 10599.98,477.93 10840.71,477.93 10861.89,499.11 v2(10861.89,664.77) 10921.91,664.77 11077.81,508.87 11506.23,508.87 11662.13,664.77 13386.49,664.77 13572.52,478.75 14247.72,478.75 14433.79,664.82 ; v1@9887.43,664.8 ccw(c9906.51,664.8) 9893.02,651.31 ; v1(10511.49,1719.89) 10929.14,1719.89 v1(10995.6,1786.34) ; v1@10517.06,1714.32 cw(c10530.5,1700.88) 10530.5,1719.89 cw(c10530.5,1738.9) v1@10517.06,1725.46 ; v2@10857.71,660.6 cw(c10847.63,650.51) 10861.89,650.51 cw(c10876.15,650.51) 10866.06,660.6 cw(c10876.15,650.51) 10876.15,664.77 cw(c10876.15,679.03) v2@10866.06,668.95 ; v1@10987.72,1786.34 cw(c10968.71,1786.34) 10982.15,1772.9 cw(c10995.6,1759.46) v1@10995.6,1778.47 ; 11833.87,664.77 ccw(c11833.87,683.92) v1@11847.41,670.38 ; 11834.07,664.77 cw(c11834.07,645.9) v1@11847.41,659.25 ; v1@11858.54,659.25 cw(c11871.89,645.9) 11871.89,664.77 ; v1@11858.54,670.38 ccw(c11872.09,683.92) 11872.09,664.77 ; 12581.94,664.77 ccw(c12581.94,683.87) v1@12595.44,670.37 ; 12582.06,664.77 cw(c12582.06,645.85) v1@12595.44,659.23 ; v1@12606.58,659.23 cw(c12619.96,645.85) 12619.96,664.77 ; v1@12606.58,670.37 ccw(c12620.08,683.87) 12620.08,664.77 ; 13329.86,664.77 ccw(c13329.86,684.03) v1@13343.47,670.41 ; 13330.2,664.77 cw(c13330.2,646.01) v1@13343.47,659.28 ; v1@13354.61,659.28 cw(c13367.88,646.01) 13367.88,664.77 ; v1@13354.61,670.41 ccw(c13368.22,684.03) 13368.22,664.77 ; 14433.74,664.77 14976.06,664.77 15174.76,466.08 v1(15864.03,466.08) ; 14651.47,664.77 cw(c14651.47,640.87) v1@14668.38,657.77 ; 14658.4,664.77 ccw(c14658.4,678.89) v1@14668.38,668.91 ; v1@14679.51,657.77 cw(c14696.42,640.87) 14696.42,664.77 ; v1@14679.51,668.91 ccw(c14689.49,678.89) 14689.49,664.77 ; v1@15858.47,460.51 ccw(c15845.03,447.07) 15845.03,466.08 ccw(c15845.03,485.09) v1@15858.47,471.64
  Bottom Layer w7.87: LED92.G@529.16,598.62 v1(580.64,598.62) ; v1@575.08,593.06 ccw(c561.63,579.61) 561.63,598.62 ccw(c561.63,617.63) v1@575.08,604.19 ; v1@1458.63,659.24 cw(c1445.19,645.8) 1464.2,645.8 cw(c1483.21,645.8) v1@1469.76,659.24 ; LED93.G@1464.2,598.62 v1(1464.2,664.81) ; v1@2393.67,659.24 cw(c2380.23,645.79) 2399.24,645.79 cw(c2418.25,645.79) v1@2404.8,659.24 ; LED94.G@2399.24,598.62 v1(2399.24,664.8) ; v1@5198.79,659.25 cw(c5185.35,645.81) 5204.35,645.81 cw(c5223.36,645.81) v1@5209.92,659.25 ; LED95.G@5204.35,598.62 v1(5204.35,664.82) ; v1@8003.9,659.22 cw(c7990.46,645.78) 8009.47,645.78 cw(c8028.48,645.78) v1@8015.04,659.22 ; LED96.G@8009.47,598.62 v1(8009.47,664.79) ; v1@8938.94,659.24 cw(c8925.5,645.8) 8944.51,645.8 cw(c8963.52,645.8) v1@8950.08,659.24 ; LED97.G@8944.51,598.62 v1(8944.51,664.81) ; v1@9873.98,659.24 cw(c9860.54,645.79) 9879.55,645.79 cw(c9898.56,645.79) v1@9885.12,659.24 ; LED98.G@9879.55,598.62 v1(9879.55,664.8) ; v1@10505.93,1714.32 cw(c10492.48,1700.88) 10511.49,1700.88 cw(c10530.5,1700.88) v1@10517.06,1714.32 ; v1(10511.49,1719.89) 10511.49,1147.68 10861.89,797.28 v2(10861.89,664.77) 10861.89,607.39 10853.12,598.62 ; LED99.G@10814.59,598.62 10853.12,598.62 ; LED99.G@10840.08,591.37 cw(c10853.12,583.29) 10853.12,598.62 ; LED99.G@10840.08,605.88 ccw(c10853.12,613.96) 10853.12,598.62 ; v2@10857.71,660.6 cw(c10847.63,650.51) 10861.89,650.51 cw(c10876.15,650.51) v2@10866.06,660.6 ; v2@10857.71,668.95 ccw(c10847.63,679.03) 10861.89,679.03 ccw(c10876.15,679.03) v2@10866.06,668.95 ; v1@10990.03,1791.91 ccw(c10976.59,1805.35) 10995.6,1805.35 ccw(c11014.61,1805.35) v1@11001.16,1791.91 ; v1(10995.6,1786.34) RR18.2@10995.6,1841.58 ; v1@11847.41,659.25 cw(c11833.97,645.8) 11852.98,645.8 cw(c11871.99,645.8) v1@11858.54,659.25 ; LED100.G@11852.98,598.62 v1(11852.98,664.81) ; v1@12595.44,659.23 cw(c12582,645.79) 12601.01,645.79 cw(c12620.02,645.79) v1@12606.58,659.23 ; LED101.G@12601.01,598.62 v1(12601.01,664.8) ; v1@13343.47,659.28 cw(c13330.03,645.83) 13349.04,645.83 cw(c13368.05,645.83) v1@13354.61,659.28 ; LED102.G@13349.04,598.62 v1(13349.04,664.84) ; v1@14668.38,657.77 cw(c14655.18,644.58) 14673.84,644.58 ; LED103.G@14673.84,598.62 v1@14673.84,664.79 ; 14673.84,644.08 cw(c14693.2,644.08) v1@14679.51,657.77 ; LED104.G@15795.89,598.62 15851.98,598.62 15864.03,586.57 v1(15864.03,466.08) ; v1@15858.47,471.64 ccw(c15845.03,485.09) 15864.03,485.09 ccw(c15883.04,485.09) v1@15869.6,471.64
  other v1: 14673.95,663.34
IIC_SCL: U1.14
IIC_SDA: U1.15
IRR1: 
IRR2: 
IRR3: 
IRR4: 
IRR5: 
IRR6: 
IRR7: 
IRR8: 
K_CIRCLE_MODE: 
K_MUTE: 
K_ON/OFF_LED: 
K_PAD_CIRCLE_MODE: 
LB0: RL2.1 U1.2 | length 927.6
  Bottom Layer w7.87: U1.2@11880.59,1636.23 11973.11,1636.23 12030.19,1693.32 12478.03,1693.32 12579.74,1795.02 RL2.1@12579.74,1905.47 ; RL2.1@12569.99,1895.73 cw(c12546.47,1872.21) 12579.74,1872.21 cw(c12613,1872.21) RL2.1@12589.48,1895.73
LB1: RL5.1 U1.6 | length 1293.4
  Bottom Layer w7.87: U1.6@11880.59,1573.24 12564.64,1573.24 12853.03,1861.62 12957.69,1861.62 12973.44,1877.37 ; RL5.1@12964.44,1897 cw(c12947.51,1877.37) 12973.43,1877.37 ; RL5.1@12973.44,1907.44 12973.44,1877.37 ; RL5.1@12982.43,1897 ccw(c12999.36,1877.37) 12973.44,1877.37
LB2: RL8.1 U1.9 | length 1192
  Bottom Layer w7.87: U1.9@11880.59,1525.99 12948.5,1525.99 12975.74,1553.22 RL8.1@13009.09,1553.22 ; RL8.1@12999.34,1543.48 ccw(c12975.82,1519.96) 12975.82,1553.22 ccw(c12975.82,1586.49) RL8.1@12999.34,1562.97
LB3: RL11.1 U1.12 | length 1430.3
  Bottom Layer w7.87: U1.12@11880.59,1478.75 12869.76,1478.75 12959.33,1389.18 12959.33,1178.55 12978.36,1159.52 ; RL11.1@12998.8,1150.36 ccw(c12978.36,1132.15) 12978.36,1159.52 ; RL11.1@12998.8,1168.69 cw(c12978.36,1186.89) 12978.36,1159.52 ; RL11.1@13009.09,1159.52 12978.36,1159.52
LB4: RL14.1 U1.42 | length 584.1
  Bottom Layer w7.87: RL14.1@11254.57,1200.12 11290.05,1200.12 11313.7,1223.77 11313.7,1477.44 11393.75,1557.49 U1.42@11542.01,1557.49
LB5: RL17.1 U1.45 | length 303.2
  Bottom Layer w7.87: RL17.1@11261.94,1660.67 11317.88,1604.73 U1.45@11542.01,1604.73
LED1: 
LED2: 
LED3: 
LED4: 
LED_SDB: U1.32
LEDA1: 
LEDA2: 
LEDA3: 
LEDA4: 
LG0: RL3.1 U1.4 | length 1087.6
  Bottom Layer w7.87: U1.4@11880.59,1604.73 12546.93,1604.73 12711.62,1769.43 RL3.1@12711.62,1905.47 ; RL3.1@12701.88,1895.73 cw(c12678.36,1872.21) 12711.62,1872.21 cw(c12744.89,1872.21) RL3.1@12721.37,1895.73
LG1: RL6.1 U1.7 | length 1437.4
  Bottom Layer w7.87: U1.7@11880.59,1557.49 12573.5,1557.49 12860.9,1844.89 13075.8,1844.89 13105.33,1874.42 ; RL6.1@13095.85,1896.46 cw(c13074.97,1874.42) 13105.32,1874.42 ; RL6.1@13105.33,1906.46 13105.33,1874.42 ; RL6.1@13114.8,1896.46 ccw(c13135.68,1874.42) 13105.33,1874.42
LG2: RL9.1 U1.10 | length 1218.6
  Bottom Layer w7.87: U1.10@11880.59,1510.24 12885.51,1510.24 12974.06,1421.69 RL9.1@13010.22,1421.69 ; RL9.1@13000.48,1411.95 ccw(c12976.95,1388.43) 12976.95,1421.69 ccw(c12976.95,1454.96) RL9.1@13000.48,1431.44
LG3: RL12.1 U1.13 | length 1533.5
  Bottom Layer w7.87: U1.13@11880.59,1463 12861.89,1463 12941.61,1383.28 12941.61,1069.3 12978.36,1032.56 ; RL12.1@12997.59,1023.65 ccw(c12978.36,1007.34) 12978.36,1032.56 ; RL12.1@12997.59,1041.46 cw(c12978.36,1057.77) 12978.36,1032.56 ; RL12.1@13008.1,1032.56 12978.36,1032.56
LG4: RL15.1 U1.43 | length 454.2
  Bottom Layer w7.87: RL15.1@11254.57,1350.73 11287.51,1350.73 11299.83,1363.05 11299.83,1483.19 11389.87,1573.24 U1.43@11542.01,1573.24 ; RL15.1@11255.94,1359.16 RL15.1@11258.94,1362.16
LG5: RL18.1 U1.46 | length 445
  Bottom Layer w7.87: RL18.1@11254.57,1818.07 11295.65,1776.98 11295.65,1647.8 11322.97,1620.48 U1.46@11542.01,1620.48
LR0: RL1.1 U1.1 | length 805.4
  Bottom Layer w7.87: U1.1@11880.59,1651.98 11962.28,1651.98 12020.35,1710.05 12387.48,1710.05 12449.81,1772.38 RL1.1@12449.81,1906.46 ; RL1.1@12440.07,1896.71 cw(c12416.55,1873.19) 12449.81,1873.19 cw(c12483.08,1873.19) RL1.1@12459.56,1896.71
LR1: RL4.1 U1.5 | length 1111.9
  Bottom Layer w7.87: U1.5@11880.59,1588.98 12555.79,1588.98 12843.51,1876.71 RL4.1@12843.51,1906.46
LR2: RL7.1 U1.8 | length 1226.1
  Bottom Layer w7.87: U1.8@11880.59,1541.74 12838.09,1541.74 12980.98,1684.63 ; RL7.1@12997.75,1676.3 ccw(c12980.98,1663.58) 12980.98,1684.63 ; RL7.1@12997.75,1692.96 cw(c12980.98,1705.68) 12980.98,1684.63 ; RL7.1@13008.73,1684.63 12980.98,1684.63
LR3: RL10.1 U1.11 | length 1300.5
  Bottom Layer w7.87: U1.11@11880.59,1494.5 12877.64,1494.5 12977.05,1395.09 12977.05,1300.6 12988.2,1289.44 ; RL10.1@13000.1,1282.57 ccw(c12988.2,1275.71) 12988.2,1289.44 ; RL10.1@13000.1,1296.32 cw(c12988.2,1303.18) 12988.2,1289.44 ; RL10.1@13012.04,1289.44 12988.2,1289.44
LR4: RL13.1 U1.41 | length 718.6
  Bottom Layer w7.87: RL13.1@11254.57,1059.48 11310.39,1059.48 11327.58,1076.67 11327.58,1471.7 11397.62,1541.74 U1.41@11542.01,1541.74
LR5: RL16.1 U1.44 | length 325
  Bottom Layer w7.87: RL16.1@11254.57,1498.25 11295.27,1498.25 11386,1588.98 U1.44@11542.01,1588.98
LRB0: 
LRG0: 
LRR0: 
MCUVDD: CA6.1 CA8.2 CA10.2 CA11.2 pad.11 R4.2 R4A.1 R4A.2 RA5.2 U1.16 U1.33 U1.55 | length 3295.2
  Top Layer w15.75: v1(11514.13,1129.3) v1(12023.74,1129.3) ; v1(11797,1957.81) 11827.7,1957.81 12066.98,1718.54 v1@12066.98,1293.06
  Bottom Layer w7.87: CA11.2@11480.2,1298.83 ccw(c11459.31,1319.72) 11488.86,1319.72 ; CA11.2@11488.86,1288 11488.86,1398.04 11506.57,1415.75 U1.33@11542.01,1415.75 ; 11488.86,1324.98 ccw(c11525.84,1324.98) CA11.2@11499.69,1298.83 ; U1.55@11687.68,1703.16 11687.68,1848.49 11726.11,1886.93 ; pad.11@11728.25,1913.61 cw(c11711.52,1901.52) 11726.11,1886.93 ; 11732.65,1893.46 ccw(c11719.11,1907.01) pad.11@11734.63,1918.23 ; 11739.18,1900 ccw(c11726.69,1912.49) pad.11@11741.01,1922.84 ; pad.11@11755.54,1916.55 cw(c11775.4,1896.7) 11775.4,1924.78 ; pad.11@11755.93,1935.64 ccw(c11780.7,1958.46) 11780.7,1924.78 ; pad.11@11761.11,1910.99 cw(c11794.41,1877.69) CA10.2@11794.41,1924.78 ; pad.11@11761.72,1940.97 ccw(c11798.66,1975.01) CA10.2@11798.66,1924.78 11763.96,1924.78 11726.11,1886.93 ; U1.16@11880.59,1415.75 11938.59,1415.75 CA8.2@11963.21,1391.13 CA8.2@11963.74,1390.6
  Bottom Layer w15.75: CA11.2@11482.99,1282.12 cw(c11468.81,1267.95) 11488.86,1267.95 ; 11488.86,1262.7 cw(c11516.33,1262.7) CA11.2@11496.91,1282.12 ; CA11.2@11489.95,1289.08 11488.86,1288 11488.86,1154.93 v1@11514.31,1129.48 ; CA8.2@11956.25,1384.17 cw(c11938.17,1366.09) 11963.74,1366.09 ; R4A.2@11956.78,1281.86 ccw(c11939.98,1298.66) 11963.74,1298.66 ccw(c11987.5,1298.66) R4A.2@11970.7,1281.86 ; R4.2@11956.78,1325.65 cw(c11939.98,1308.84) 11963.74,1308.84 cw(c11987.5,1308.84) R4.2@11970.7,1325.65 ; R4.2@11956.78,1339.57 ccw(c11939.98,1356.37) 11963.74,1356.37 ccw(c11987.5,1356.37) R4.2@11970.7,1339.57 ; R4A.2@11963.74,1274.9 R4.2@11963.74,1332.61 CA8.2@11963.74,1390.6 ; 11963.74,1368.65 cw(c11985.69,1368.65) CA8.2@11970.17,1384.17 ; R4A.1@12016.78,1267.94 cw(c11999.98,1251.13) 12023.74,1251.13 cw(c12047.5,1251.13) 12030.7,1267.94 cw(c12047.5,1251.13) 12047.5,1274.9 cw(c12047.5,1298.66) R4A.1@12030.7,1281.86 ; R4A.1@12021.73,1269.34 ccw(c12030.82,1294.42) 12049.69,1275.56 ; v1(12023.74,1129.3) R4A.1@12023.74,1274.9 12049.02,1274.9 v1(12067.19,1293.06)
  Bottom Layer w19.68: CA6.1@11784.09,1990.79 cw(c11748.92,1955.61) v1@11798.66,1955.61 ; CA6.1@11784.09,2059.29 ccw(c11748.92,2094.47) 11798.66,2094.47 ; CA10.2@11793.1,1930.35 ccw(c11779.65,1943.79) 11798.66,1943.79 ccw(c11817.67,1943.79) CA10.2@11804.23,1930.35 ; CA10.2@11798.66,1924.78 RA5.2@11798.66,2127.96 ; v1@11798.66,1957.14 cw(c11846.25,1957.14) CA6.1@11812.6,1990.79 ; 11798.66,2092.94 ccw(c11846.25,2092.94) CA6.1@11812.6,2059.29 ; 11798.66,2101.54 cw(c11820.28,2101.54) RA5.2@11804.99,2116.83
NetCA1_1: 
NetCA4_1: 
NetCA11_1: 
NetCONA1_2: pad.5 RA3.1 USB.3 | length 1333.1
  Bottom Layer w7.87: 11225.92,2785.42 cw(c11328.45,2785.42) pad.5@11255.95,2857.92 ; 11225.92,2804.43 cw(c11309.44,2804.43) pad.5@11250.38,2863.49 ; 11225.92,2823.44 cw(c11290.43,2823.44) pad.5@11244.82,2869.06 ; 11225.92,2842.45 cw(c11271.42,2842.45) pad.5@11239.25,2874.62 ; pad.5@11225.92,2871.23 USB.3@11225.92,2531.38 11225.92,2501.65 11194.54,2470.27 11194.54,2124.42 11240.4,2078.56 11478.27,2078.56 11486.16,2070.67 RA3.1@11486.16,2043.81
NetCONA1_3: pad.4 RA2.1 USB.4 | length 1173.1
  Bottom Layer w7.87: USB.4@11147.18,2531.38 11147.18,2501.67 11176.09,2472.77 11176.09,2116.48 11235.2,2057.38 11243.33,2057.38 11243.5,2057.2 RA2.1@11433.79,2057.2
  Bottom Layer w9.84: pad.4@11132.57,2861.3 cw(c11097.28,2826.02) 11147.18,2826.02 cw(c11197.08,2826.02) pad.4@11161.8,2861.3 ; pad.4@11139.53,2868.26 cw(c11121.05,2849.78) 11147.18,2849.78 cw(c11173.32,2849.78) pad.4@11154.84,2868.26 ; USB.4@11147.18,2531.38 pad.4@11147.18,2875.92
NetCONA1_4: 
NetCONA1_5: 
NetIR1_1: 
NetIR1_2: 
NetIR2_2: 
NetIR3_2: 
NetIR4_2: 
NetIR5_2: 
NetIR6_2: 
NetIR7_2: 
NetIR8_2: 
NetIR9_2: 
NetIR10_2: 
NetIR11_2: 
NetIR12_2: 
NetIR13_2: 
NetIR14_2: 
NetIR15_2: 
NetIR16_1: 
NetIR31_1: 
NetIR46_1: 
NetIR61_1: 
NetIR76_1: 
NetIR91_1: 
NetIR100_1: 
NetKB1_1: NUM.1 RB1.1 | length 650.4
  Bottom Layer w7.87: NUM.1@14392.4,4341.94 14451.46,4282.88 14451.46,3816.35 14423.71,3788.6 ; RB1.1@14397.49,3788.6 14423.71,3788.6 ; RB1.1@14408.85,3780.78 cw(c14423.71,3770.56) 14423.71,3788.6 ; RB1.1@14408.85,3796.41 ccw(c14423.71,3806.64) 14423.71,3788.6
NetKB2_1: CAPS.1 RB2.1 | length 556
  Bottom Layer w7.87: CAPS.1@15010.31,4307.08 15107.19,4307.08 15144.54,4269.73 RB2.1@15144.54,3863.4
NetKB3_1: RB3.1 SCR.1 | length 647.6
  Bottom Layer w7.87: SCR.1@15600.87,4307.08 15741.43,4307.08 15889.62,4158.9 RB3.1@15889.62,3861.43
NetKB4_1: RB4.1 WIN.1 | length 778.1
  Bottom Layer w7.87: WIN.1@16191.42,4307.08 16341.87,4307.08 16638.64,4010.31 RB4.1@16638.64,3802.38
NetLED1_A: 
NetLED1_K: 
NetLED2_K: 
NetLED3_K: 
NetLED4_K: 
NetLED5_K: 
NetLED6_K: 
NetLED7_K: 
NetLED8_K: 
NetLED9_K: 
NetLED10_K: 
NetLED11_K: 
NetLED12_K: 
NetLED13_K: 
NetLED14_K: 
NetLED15_K: 
NetLED16_A: 
NetLED31_A: 
NetLED46_A: 
NetLED61_A: 
NetLED76_A: 
NetLED91_A: 
NetLED100_A: 
NetLED108_2: 
NetLED109_2: 
NetLED110_2: 
NetLED111_2: 
NetLED112_1: 
NetLED112_2: 
NetLED112_3: 
NetLED113_VDD: 
NetLED117_2: 
NetQ1_B: 
NetQ2_B: 
NetQ3_B: 
NetQ4_B: 
NetQ5_B: 
NetQ6_B: 
NetQ7_B: 
NetQ8_B: 
NetQ9_B: 
NetQ10_B: 
NetQ11_B: 
NetQ12_B: 
NetQ13_B: 
NetQ14_B: 
NetQ15_B: 
NetQ16_B: 
NetQ16_C: 
NetQ17_B: 
NetQ17_C: 
NetQ18_B: 
NetQ18_C: 
NetQ19_B: 
NetQ19_C: 
NetQ20_B: 
NetQ20_C: 
NetQ21_B: 
NetQ21_C: 
NetQ22_B: 
NetQ22_C: 
NetQ23_B: 
NetQ23_C: 
NetQ24_B: 
NetQ25_B: 
NetQ26_B: 
NetQ27_B: 
NetQ28_B: 
NetQ29_B: 
NetQ30_B: 
NetQ31_B: 
NetQ32_B: 
NetQ33_B: 
NetQ34_B: 
NetQ35_B: 
NetQ36_B: 
NetQ37_B: 
NetQ38_B: 
NetQ39_B: 
NetQ39_C: 
NetQ40_B: 
NetQ40_C: 
NetQ41_B: 
NetQ41_C: 
NetQ42_B: 
NetQ42_C: 
NetR19_1: 
NetR30_2: 
NetRA1_1: 
NetRB1_2: Q36.C RB1.2 RC18.2 | length 243
  Bottom Layer w19.68: Q36.C@14260.51,3729.73 RC18.2@14337.28,3729.73 ; Q36.C@14273.28,3736.48 ccw(c14289.58,3752.79) 14289.58,3729.73 ; 14317.77,3729.73 ccw(c14317.77,3749.75) 14331.93,3735.59 ccw(c14318.48,3749.04) 14337.49,3749.04 ccw(c14356.5,3749.04) RC18.2@14343.06,3735.59 ; 14319.2,3729.73 cw(c14319.2,3711.73) RC18.2@14331.93,3724.46 ; RB1.2@14331.93,3783.03 cw(c14318.48,3769.59) 14337.49,3769.59 cw(c14356.5,3769.59) RB1.2@14343.06,3783.03 ; RC18.2@14337.49,3730.03 RB1.2@14337.49,3788.6
NetRB2_2: Q37.C RB2.2 RC19.2 | length 317.9
  Bottom Layer w19.68: Q37.C@15007.56,3729.73 15084.33,3729.73 RB2.2@15084.33,3863.19 ; Q37.C@15020.33,3723.96 cw(c15034.25,3710.04) 15034.25,3729.73 cw(c15034.25,3749.43) Q37.C@15020.33,3735.5 ; 15064.09,3729.73 cw(c15064.09,3710.07) RC19.2@15077.99,3723.97 ; 15065.01,3729.73 ccw(c15065.01,3748.09) 15077.99,3735.11 ccw(c15062.68,3750.42) 15084.33,3750.42 ; RB2.2@15078.97,3857.83 cw(c15066.05,3844.9) 15084.33,3844.9 ; 15084.33,3843.88 cw(c15104.07,3843.88) RB2.2@15090.11,3857.83
NetRB3_2: Q38.C RB3.2 RC20.2 | length 294.1
  Bottom Layer w19.68: Q38.C@15754.61,3729.73 RC20.2@15831.38,3729.73 ; Q38.C@15767.37,3722.98 cw(c15783.67,3706.68) 15783.67,3729.73 ; 15805.59,3729.73 cw(c15805.59,3705.01) RC20.2@15823.07,3722.49 ; RC20.2@15823.07,3733.63 ccw(c15809.63,3747.07) 15828.64,3747.07 ccw(c15847.65,3747.07) RC20.2@15834.2,3733.63 ; RC20.2@15828.64,3728.06 RB3.2@15828.64,3860.45 ; 15828.64,3840.05 cw(c15851.01,3840.05) RB3.2@15835.19,3855.86
NetRB4_2: Q39.C RB4.2 RC21.2 | length 269.2
  Bottom Layer w19.68: Q39.C@16503.62,3728.75 16578.93,3728.75 RB4.2@16578.93,3802.08 ; Q39.C@16516.39,3722.98 cw(c16530.31,3709.05) 16530.31,3728.75 cw(c16530.31,3748.44) Q39.C@16516.39,3734.52 ; 16559.65,3728.75 cw(c16559.65,3709.09) RC21.2@16573.55,3722.99 ; 16560.57,3728.75 ccw(c16560.57,3747.11) 16573.55,3734.13 ccw(c16560.57,3747.11) 16578.93,3747.11 ; RB4.2@16573.07,3796.81 cw(c16558.92,3782.66) 16578.93,3782.66 ; 16578.93,3748.03 ccw(c16598.59,3748.03) RC21.2@16584.69,3734.13 ; 16578.93,3784.08 cw(c16596.94,3784.08) RB4.2@16584.2,3796.81
NetRC1_2: Q19.C RC1.2 | length 138.6
  Bottom Layer w19.68: Q19.C@396.34,3728.75 RC1.2@474.09,3728.75 ; Q19.C@409.11,3722.98 cw(c423.03,3709.05) 423.03,3728.75 cw(c423.03,3748.44) Q19.C@409.11,3734.52 ; 449.66,3728.75 ccw(c449.66,3748.76) RC1.2@463.82,3734.61 ; 451.09,3728.75 cw(c451.09,3710.75) RC1.2@463.82,3723.48
NetRC2_2: Q20.C RC2.2 | length 137.6
  Bottom Layer w19.68: Q20.C@1141.42,3729.73 RC2.2@1218.19,3729.73 ; Q20.C@1154.18,3723.96 cw(c1168.11,3710.04) 1168.11,3729.73 cw(c1168.11,3749.43) Q20.C@1154.18,3735.5 ; 1197.69,3729.73 ccw(c1197.69,3749.75) RC2.2@1211.85,3735.59 ; 1199.12,3729.73 cw(c1199.12,3711.73) RC2.2@1211.85,3724.46
NetRC3_2: Q21.C RC3.2 | length 111.7
  Bottom Layer w19.68: Q21.C@1890.43,3729.73 RC3.2@1967.2,3729.73 ; Q21.C@1903.2,3722.98 cw(c1919.5,3706.68) 1919.5,3729.73 ; 1937.88,3729.73 cw(c1937.88,3708.37) RC3.2@1952.99,3723.48
NetRC4_2: Q22.C RC4.2 | length 111.7
  Bottom Layer w19.68: Q22.C@2639.45,3729.73 RC4.2@2716.22,3729.73 ; Q22.C@2652.22,3722.98 cw(c2668.52,3706.68) 2668.52,3729.73 ; 2689.85,3729.73 cw(c2689.85,3708.37) RC4.2@2704.96,3723.48
NetRC5_2: Q23.C RC5.2 | length 111.7
  Bottom Layer w19.68: Q23.C@3388.46,3729.73 RC5.2@3465.24,3729.73 ; Q23.C@3401.23,3722.98 cw(c3417.53,3706.68) 3417.53,3729.73 ; 3441.82,3729.73 cw(c3441.82,3708.37) RC5.2@3456.93,3723.48
NetRC6_2: Q24.C RC6.2 | length 111.7
  Bottom Layer w19.68: Q24.C@4135.51,3729.73 RC6.2@4212.28,3729.73 ; Q24.C@4148.28,3722.98 cw(c4164.58,3706.68) 4164.58,3729.73 ; 4188.87,3729.73 cw(c4188.87,3708.37) RC6.2@4203.97,3723.48
NetRC7_2: Q25.C RC7.2 | length 111.9
  Bottom Layer w19.68: Q25.C@4882.56,3729.73 RC7.2@4959.33,3729.73 ; Q25.C@4895.33,3736.48 ccw(c4911.63,3752.79) 4911.63,3729.73 ; 4933.69,3729.73 ccw(c4933.69,3751.45) RC7.2@4949.05,3736.09
NetRC8_2: Q26.C RC8.2 | length 113
  Bottom Layer w19.68: Q26.C@5631.57,3729.73 RC8.2@5708.35,3729.73 ; Q26.C@5644.34,3722.98 cw(c5660.64,3706.68) 5660.64,3729.73 ; 5682.78,3729.73 cw(c5682.78,3706.71) RC8.2@5699.05,3722.99
NetRC9_2: Q27.C RC9.2 | length 114.3
  Bottom Layer w19.68: Q27.C@6377.64,3729.73 RC9.2@6454.41,3729.73 ; Q27.C@6390.4,3722.98 cw(c6406.71,3706.68) 6406.71,3729.73 ; 6429.6,3729.73 cw(c6429.6,3705.01) RC9.2@6447.08,3722.49
NetRC10_2: Q28.C RC10.2 | length 114.3
  Bottom Layer w19.68: Q28.C@7126.65,3729.73 RC10.2@7203.42,3729.73 ; Q28.C@7139.42,3722.98 cw(c7155.72,3706.68) 7155.72,3729.73 ; 7179.6,3729.73 cw(c7179.6,3705.01) RC10.2@7197.08,3722.49
NetRC11_2: Q29.C RC11.2 | length 111.7
  Bottom Layer w19.68: Q29.C@7876.65,3729.73 RC11.2@7953.42,3729.73 ; Q29.C@7889.42,3722.98 cw(c7905.72,3706.68) 7905.72,3729.73 ; 7930.99,3729.73 cw(c7930.99,3708.37) RC11.2@7946.1,3723.48
NetRC12_2: Q30.C RC12.2 | length 113
  Bottom Layer w19.68: Q30.C@8622.72,3729.73 RC12.2@8699.49,3729.73 ; Q30.C@8635.48,3722.98 cw(c8651.78,3706.68) 8651.78,3729.73 ; 8672.93,3729.73 cw(c8672.93,3706.71) RC12.2@8689.21,3722.99
NetRC13_2: Q31.C RC13.2 | length 114.3
  Bottom Layer w19.68: Q31.C@9370.75,3729.73 RC13.2@9447.52,3729.73 ; Q31.C@9383.51,3722.98 cw(c9399.82,3706.68) 9399.82,3729.73 ; 9421.73,3729.73 cw(c9421.73,3705.01) RC13.2@9439.21,3722.49
NetRC14_2: Q32.C RC14.2 | length 184.2
  Bottom Layer w11.81: Q32.C@10492.79,3728.75 10492.79,3825.41 10518.41,3851.03 RC14.2@10569.71,3851.03
NetRC15_2: Q33.C RC15.2 | length 111.7
  Bottom Layer w19.68: Q33.C@11812.68,3729.73 RC15.2@11889.45,3729.73 ; Q33.C@11825.44,3722.98 cw(c11841.75,3706.68) 11841.75,3729.73 ; 11867.02,3729.73 cw(c11867.02,3708.37) RC15.2@11882.12,3723.48
NetRC16_2: Q34.C RC16.2 | length 113
  Bottom Layer w19.68: Q34.C@12560.71,3729.73 RC16.2@12637.48,3729.73 ; Q34.C@12573.48,3722.98 cw(c12589.78,3706.68) 12589.78,3729.73 ; 12614.36,3729.73 cw(c12614.36,3706.71) RC16.2@12630.64,3722.99
NetRC17_2: Q35.C RC17.2 | length 137.6
  Bottom Layer w19.68: Q35.C@13308.74,3729.73 RC17.2@13385.51,3729.73 ; Q35.C@13321.51,3723.96 cw(c13335.43,3710.04) 13335.43,3729.73 cw(c13335.43,3749.43) Q35.C@13321.51,3735.5 ; 13367.72,3729.73 cw(c13367.72,3710.07) RC17.2@13381.62,3723.97 ; 13368.64,3729.73 ccw(c13368.64,3748.09) RC17.2@13381.62,3735.11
